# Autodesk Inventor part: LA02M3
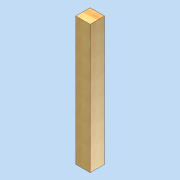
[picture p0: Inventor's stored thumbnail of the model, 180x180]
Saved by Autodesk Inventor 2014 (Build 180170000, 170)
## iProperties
Created: 2011-04
Part Number: LA02M3
Document SubType Name: Modeling
Designer: david.appleford
Density: 0.44 g/cm^3
Description: Lug Middle 0.5w 3 Slots
Mass: 1237.01 g
Surface Area: 1746.24 cm^2
Volume: 2811.39 cm^3
Cost Center: £6.00
Material: 000 Redwood
Appearance: Wood (Pine)
Justset: False
Author: david.appleford
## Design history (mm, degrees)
sketch "Sketch1"
  geometry: L1 (0, 0)-(68, 0); L2 (68, 0)-(68, 68); L3 (68, 68)-(0, 68); L4 (0, 68)-(0, 0)
  constraints: 8 end point, 2 parallel, 1 horizontal, 1 perpendicular
  dimensions: "d0" = 68 distance between parallel lines of L2 L4 (= t); "d1" = 68 distance between parallel lines of L1 L3 (= t)
extrude "Extrusion1" new body sketch "Sketch1" distance "d2" = 608 (= 0.5 x w - Cl); taper "d3" = 0 deg
body "Solid1"
other parameters: "t" = 68 [user parameter; used in 2 equation terms], "Cl" = 2 [user parameter; used in 1 equation term]
